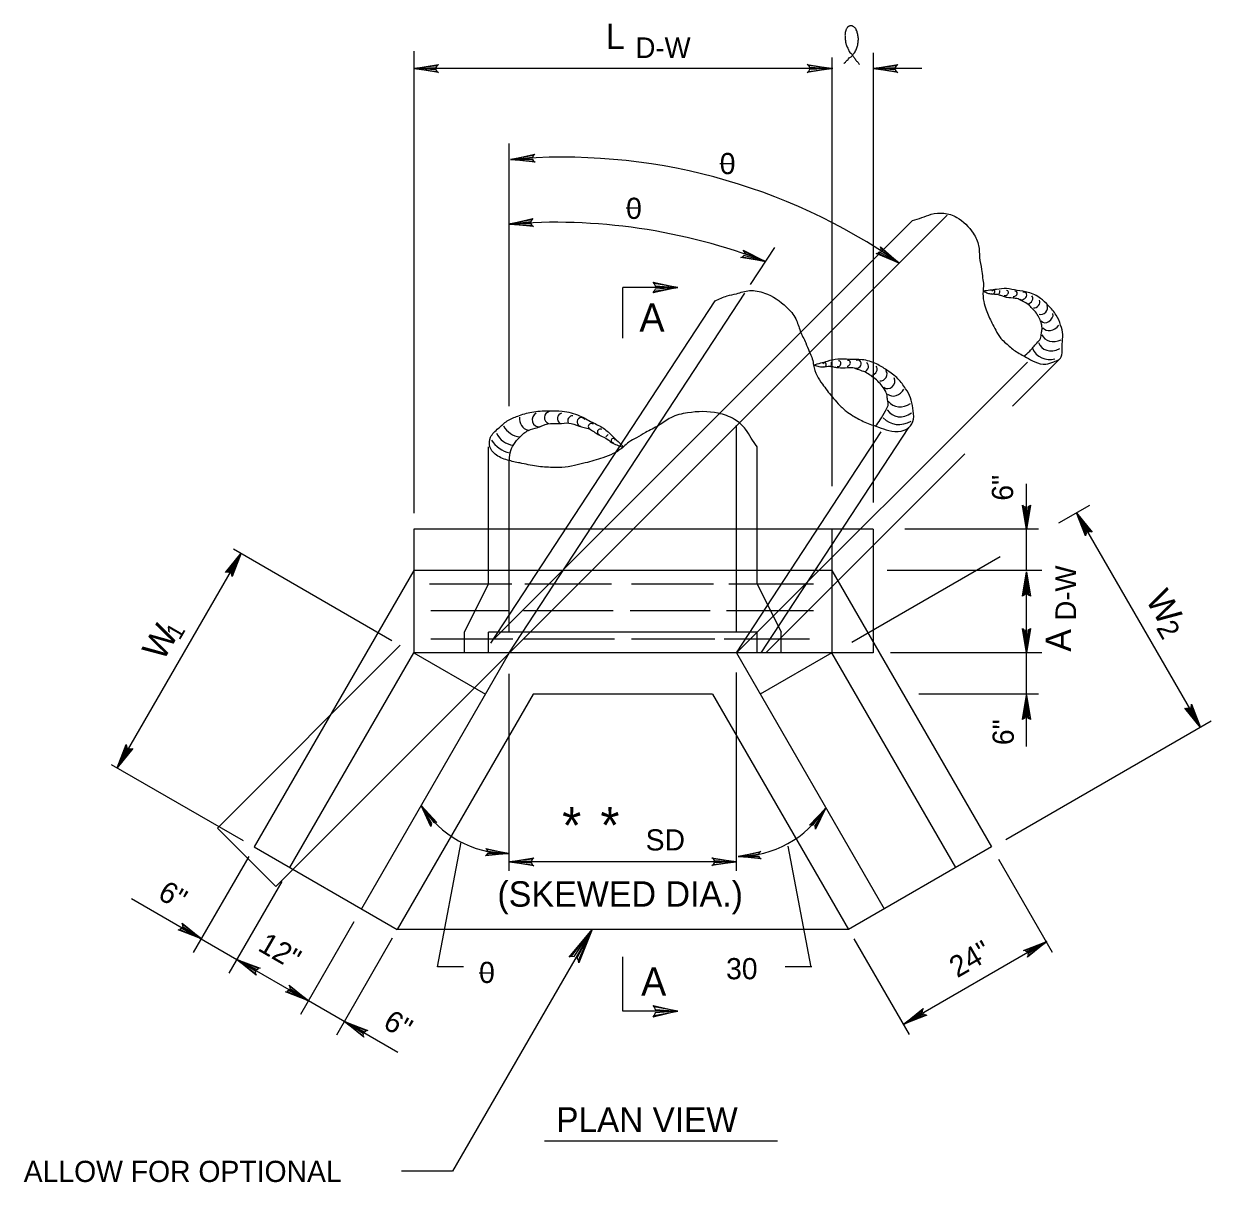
# Model space of a CAD drawing. Extents: x 638877 to 639960, y 297341 to 299123.
# Drawn here: x 639097.6 to 639265.8, y 297554.3 to 297718.4 of the extents above; entities that cross this region are included whole.
import ezdxf

# ---------------------------------------------------------------- set-up
doc = ezdxf.new("R2010")
doc.units = 0
for name, color, linetype in [('1', 7, 'Continuous'), ('2', 7, 'Continuous'), ('3', 7, 'Continuous')]:
    doc.layers.add(name, color=color, linetype=linetype)

msp = doc.modelspace()

# ---------------------------------------------------------------- linework, layer by layer
at = {"layer": '1'}
for p, q in [((639182.48, 297673.85), (639182.48, 297681.01)), ((639182.48, 297578.51), (639182.48, 297586.23))]:
    msp.add_line(p, q, dxfattribs=at)
at = {"layer": '2'}
for p, q in [((639152.88, 297714.49), (639152.88, 297649.07)), ((639212.06, 297713.59), (639212.06, 297652.88)), ((639217.91, 297714.27), (639217.91, 297650.57)), ((639212.19, 297712.03), (639152.88, 297712.03)), ((639224.79, 297712.03), (639217.91, 297712.03)), ((639166.39, 297664.23), (639166.39, 297701.43)), ((639133.32, 297596.18), (639228.39, 297691.26)), ((639164.32, 297631.32), (639223.49, 297690.49)), ((639200.55, 297681.46), (639203.98, 297686.69)), ((639190.28, 297681.01), (639182.48, 297681.01)), ((639166.39, 297629.25), (639199.75, 297680.23)), ((639163.8, 297630.64), (639195.53, 297679.13)), ((639198.56, 297629.25), (639239.75, 297670.45)), ((639237.64, 297664.2), (639244.26, 297670.81)), ((639198.56, 297632.18), (639198.56, 297661.53)), ((639202.06, 297629.25), (639222.96, 297661.19)), ((639198.56, 297629.25), (639219.04, 297660.55)), ((639163.46, 297640.95), (639163.46, 297658.46)), ((639201.49, 297640.95), (639201.49, 297658.46)), ((639166.39, 297632.18), (639166.39, 297656.31)), ((639202.7, 297629.25), (639230.89, 297657.45)), ((639220.22, 297646.77), (639227.09, 297653.64)), ((639239.63, 297640.95), (639239.63, 297653.2)), ((639248.53, 297650.15), (639244.17, 297647.63)), ((639246.73, 297649.1), (639264.28, 297618.71)), ((639211.72, 297646.8), (639152.88, 297646.8)), ((639152.88, 297646.8), (639152.88, 297629.25)), ((639217.91, 297646.8), (639211.72, 297646.8)), ((639212.06, 297646.8), (639212.06, 297629.25)), ((639217.91, 297646.8), (639217.91, 297629.25)), ((639241.35, 297646.8), (639222.38, 297646.8)), ((639127.33, 297644.01), (639149.78, 297631.04)), ((639128.41, 297643.38), (639110.86, 297612.99)), ((639235.91, 297642.86), (639214.89, 297630.72)), ((639152.88, 297640.95), (639130.26, 297601.78)), ((639212.07, 297640.95), (639152.88, 297640.95)), ((639163.46, 297639.03), (639163.46, 297640.95)), ((639201.49, 297639.04), (639201.49, 297640.95)), ((639204.76, 297633.39), (639210.08, 297641.52)), ((639212.07, 297640.95), (639234.69, 297601.78)), ((639241.79, 297640.95), (639219.91, 297640.95)), ((639239.63, 297629.26), (639239.63, 297640.75)), ((639166.74, 297639), (639155.08, 297639)), ((639160.03, 297632.18), (639163.46, 297639.03)), ((639180.88, 297639), (639168.58, 297639)), ((639195.33, 297639), (639183.68, 297639)), ((639209.47, 297639), (639197.49, 297639)), ((639201.49, 297639.04), (639204.91, 297632.18)), ((639166.42, 297635.22), (639155.29, 297635.22)), ((639181.09, 297635.22), (639168.39, 297635.22)), ((639194.82, 297635.22), (639183.49, 297635.22)), ((639209.47, 297635.22), (639197.17, 297635.22)), ((639166.9, 297631.2), (639155.29, 297631.2)), ((639160.03, 297629.25), (639160.03, 297632.18)), ((639201.49, 297632.18), (639163.46, 297632.18)), ((639163.46, 297629.25), (639163.46, 297632.18)), ((639166.39, 297632.18), (639166.39, 297632.18)), ((639181.28, 297631.2), (639168.39, 297631.2)), ((639195.49, 297631.2), (639183.68, 297631.2)), ((639208.88, 297631.2), (639196.82, 297631.2)), ((639198.56, 297632.18), (639198.56, 297632.18)), ((639201.49, 297629.25), (639201.49, 297632.18)), ((639204.91, 297629.25), (639204.91, 297632.18)), ((639125.05, 297604.46), (639150.96, 297630.37)), ((639135.33, 297598.86), (639152.88, 297629.25)), ((639166.39, 297629.25), (639145.46, 297593)), ((639212.07, 297629.25), (639152.88, 297629.25)), ((639152.88, 297629.25), (639163.01, 297623.4)), ((639166.39, 297629.25), (639166.39, 297629.25)), ((639198.56, 297629.25), (639219.49, 297593.01)), ((639198.56, 297629.25), (639198.56, 297629.25)), ((639212.07, 297629.25), (639201.94, 297623.4)), ((639217.91, 297629.25), (639212.07, 297629.25)), ((639229.62, 297598.86), (639212.07, 297629.25)), ((639241.79, 297629.25), (639220.35, 297629.25)), ((639239.63, 297616), (639239.63, 297629.25)), ((639166.39, 297598.41), (639166.39, 297626.28)), ((639198.56, 297598.41), (639198.56, 297626.47)), ((639169.77, 297623.4), (639150.53, 297590.08)), ((639195.19, 297623.4), (639169.77, 297623.4)), ((639195.19, 297623.4), (639214.43, 297590.08)), ((639241.35, 297623.4), (639224.38, 297623.4)), ((639265.79, 297619.58), (639236.69, 297602.78)), ((639110, 297613.48), (639128.72, 297602.67)), ((639133.32, 297596.18), (639125.05, 297604.46)), ((639156.23, 297584.78), (639159.59, 297602.44)), ((639129.49, 297600.44), (639121.63, 297586.83)), ((639130.26, 297601.78), (639150.53, 297590.08)), ((639209.14, 297584.76), (639205.89, 297601.88)), ((639234.69, 297601.78), (639214.43, 297590.08)), ((639234.69, 297601.78), (639214.43, 297590.08)), ((639198.56, 297599.68), (639166.39, 297599.68)), ((639235.69, 297600.06), (639243.29, 297586.9)), ((639134.18, 297596.87), (639126.7, 297583.91)), ((639112.91, 297594.47), (639127.82, 297585.86)), ((639144.4, 297591.16), (639136.83, 297578.06)), ((639149.81, 297588.84), (639141.9, 297575.13)), ((639214.43, 297590.08), (639150.53, 297590.08)), ((639178.12, 297590.08), (639158.37, 297555.86)), ((639215.19, 297588.76), (639223.02, 297575.2)), ((639242.51, 297588.39), (639222.25, 297576.68)), ((639127.81, 297585.86), (639137.97, 297580)), ((639159.91, 297584.78), (639156.23, 297584.78)), ((639209.25, 297584.78), (639205.44, 297584.78)), ((639137.96, 297580.01), (639150.59, 297572.71)), ((639190.28, 297578.51), (639182.48, 297578.51)), ((639158.37, 297555.86), (639151.13, 297555.86))]:
    msp.add_line(p, q, dxfattribs=at)
for points in [[(639156.18, 297711.61), (639156.06, 297711.85), (639152.88, 297712.03), (639156.18, 297711.61), (639156.35, 297711.47), (639152.88, 297712.03), (639156.06, 297712.18), (639156.18, 297712.42), (639152.88, 297712.03), (639156.35, 297712.58), (639156.18, 297712.42)], [(639208.76, 297712.44), (639208.88, 297712.2), (639212.06, 297712.03), (639208.76, 297712.44), (639208.59, 297712.59), (639212.06, 297712.03), (639208.88, 297711.87), (639208.77, 297711.63), (639212.06, 297712.03), (639208.59, 297711.48), (639208.77, 297711.63)], [(639221.22, 297711.61), (639221.09, 297711.85), (639217.91, 297712.03), (639221.22, 297711.61), (639221.39, 297711.47), (639217.91, 297712.03), (639221.09, 297712.18), (639221.21, 297712.42), (639217.91, 297712.03), (639221.39, 297712.58), (639221.21, 297712.42)], [(639169.87, 297698.92), (639169.74, 297699.15), (639166.55, 297699.15), (639169.87, 297698.92), (639170.05, 297698.78), (639166.55, 297699.15), (639169.72, 297699.48), (639169.82, 297699.72), (639166.55, 297699.15), (639169.99, 297699.89), (639169.82, 297699.72)], [(639169.63, 297689.8), (639169.49, 297690.03), (639166.3, 297690), (639169.63, 297689.8), (639169.81, 297689.66), (639166.3, 297690), (639169.47, 297690.36), (639169.57, 297690.61), (639166.3, 297690), (639169.73, 297690.77), (639169.57, 297690.61)], [(639199.65, 297686.12), (639199.69, 297685.86), (639202.66, 297684.71), (639199.65, 297686.12), (639199.53, 297686.31), (639202.66, 297684.71), (639199.59, 297685.54), (639199.41, 297685.35), (639202.66, 297684.71), (639199.19, 297685.25), (639199.41, 297685.35)], [(639219.02, 297686.57), (639219, 297686.3), (639221.6, 297684.47), (639219.02, 297686.57), (639218.95, 297686.78), (639221.6, 297684.47), (639218.82, 297686.02), (639218.6, 297685.88), (639221.6, 297684.47), (639218.36, 297685.84), (639218.6, 297685.88)], [(639186.92, 297681.57), (639187.05, 297681.25), (639190.28, 297681.01), (639186.92, 297681.57), (639186.75, 297681.76), (639190.28, 297681.01), (639187.05, 297680.79), (639186.93, 297680.48), (639190.28, 297681.01), (639186.75, 297680.26), (639186.93, 297680.48)], [(639240.04, 297650.03), (639239.8, 297649.91), (639239.63, 297646.73), (639240.04, 297650.03), (639240.19, 297650.2), (639239.63, 297646.73), (639239.47, 297649.91), (639239.23, 297650.02), (639239.63, 297646.73), (639239.08, 297650.2), (639239.23, 297650.02)], [(639248.02, 297646.03), (639248.17, 297646.26), (639246.73, 297649.1), (639248.02, 297646.03), (639247.98, 297645.82), (639246.73, 297649.1), (639248.45, 297646.43), (639248.71, 297646.45), (639246.73, 297649.1), (639248.94, 297646.37), (639248.71, 297646.45)], [(639126.4, 297640.73), (639126.67, 297640.72), (639128.41, 297643.38), (639126.4, 297640.73), (639126.19, 297640.65), (639128.41, 297643.38), (639126.96, 297640.55), (639127.1, 297640.33), (639128.41, 297643.38), (639127.15, 297640.1), (639127.1, 297640.33)], [(639239.21, 297637.45), (639239.45, 297637.57), (639239.63, 297640.75), (639239.21, 297637.45), (639239.07, 297637.28), (639239.63, 297640.75), (639239.78, 297637.57), (639240.02, 297637.46), (639239.63, 297640.75), (639240.18, 297637.28), (639240.02, 297637.46)], [(639240.04, 297632.56), (639239.8, 297632.44), (639239.63, 297629.26), (639240.04, 297632.56), (639240.19, 297632.73), (639239.63, 297629.26), (639239.47, 297632.44), (639239.23, 297632.55), (639239.63, 297629.26), (639239.08, 297632.73), (639239.23, 297632.55)], [(639239.21, 297619.98), (639239.45, 297620.1), (639239.63, 297623.28), (639239.21, 297619.98), (639239.07, 297619.81), (639239.63, 297623.28), (639239.78, 297620.1), (639240.02, 297619.98), (639239.63, 297623.28), (639240.18, 297619.81), (639240.02, 297619.98)], [(639262.98, 297621.78), (639262.84, 297621.55), (639264.28, 297618.71), (639262.98, 297621.78), (639263.02, 297622), (639264.28, 297618.71), (639262.55, 297621.38), (639262.29, 297621.37), (639264.28, 297618.71), (639262.06, 297621.44), (639262.29, 297621.37)], [(639112.87, 297615.64), (639112.6, 297615.65), (639110.86, 297612.99), (639112.87, 297615.64), (639113.09, 297615.72), (639110.86, 297612.99), (639112.32, 297615.82), (639112.17, 297616.04), (639110.86, 297612.99), (639112.12, 297616.27), (639112.17, 297616.04)], [(639169.69, 297599.26), (639169.57, 297599.5), (639166.39, 297599.68), (639169.69, 297599.26), (639169.86, 297599.12), (639166.39, 297599.68), (639169.57, 297599.83), (639169.68, 297600.07), (639166.39, 297599.68), (639169.86, 297600.23), (639169.68, 297600.07)], [(639195.26, 297600.09), (639195.38, 297599.85), (639198.56, 297599.68), (639195.26, 297600.09), (639195.08, 297600.24), (639198.56, 297599.68), (639195.38, 297599.52), (639195.26, 297599.28), (639198.56, 297599.68), (639195.08, 297599.13), (639195.26, 297599.28)], [(639120.13, 297590.78), (639120.12, 297590.51), (639122.79, 297588.77), (639120.13, 297590.78), (639120.06, 297590.99), (639122.79, 297588.77), (639119.96, 297590.22), (639119.74, 297590.07), (639122.79, 297588.77), (639119.5, 297590.02), (639119.74, 297590.07)], [(639175.17, 297586.3), (639175.56, 297586.27), (639178.12, 297590.08), (639175.17, 297586.3), (639174.87, 297586.19), (639178.12, 297590.08), (639175.97, 297586.03), (639176.18, 297585.71), (639178.12, 297590.08), (639176.24, 297585.37), (639176.18, 297585.71)], [(639239.44, 297587.09), (639239.67, 297586.95), (639242.51, 297588.39), (639239.44, 297587.09), (639239.22, 297587.13), (639242.51, 297588.39), (639239.84, 297586.66), (639239.85, 297586.4), (639242.51, 297588.39), (639239.78, 297586.17), (639239.85, 297586.4)], [(639130.47, 297583.85), (639130.48, 297584.12), (639127.81, 297585.86), (639130.47, 297583.85), (639130.54, 297583.64), (639127.81, 297585.86), (639130.65, 297584.41), (639130.87, 297584.56), (639127.81, 297585.86), (639131.1, 297584.6), (639130.87, 297584.56)], [(639135.32, 297582.01), (639135.3, 297581.74), (639137.97, 297580), (639135.32, 297582.01), (639135.24, 297582.22), (639137.97, 297580), (639135.14, 297581.45), (639134.92, 297581.31), (639137.97, 297580), (639134.68, 297581.26), (639134.92, 297581.31)], [(639186.92, 297579.13), (639187.05, 297578.78), (639190.28, 297578.51), (639186.92, 297579.13), (639186.75, 297579.34), (639190.28, 297578.51), (639187.05, 297578.28), (639186.93, 297577.93), (639190.28, 297578.51), (639186.75, 297577.69), (639186.93, 297577.93)], [(639225.32, 297577.98), (639225.09, 297578.12), (639222.25, 297576.68), (639225.32, 297577.98), (639225.54, 297577.94), (639222.25, 297576.68), (639224.92, 297578.41), (639224.9, 297578.67), (639222.25, 297576.68), (639224.98, 297578.9), (639224.9, 297578.67)], [(639145.72, 297575.05), (639145.73, 297575.32), (639143.06, 297577.06), (639145.72, 297575.05), (639145.79, 297574.84), (639143.06, 297577.06), (639145.89, 297575.61), (639146.11, 297575.75), (639143.06, 297577.06), (639146.35, 297575.8), (639146.11, 297575.75)]]:
    msp.add_lwpolyline(points, dxfattribs=at)
for centre, radius, start, end in [((639173.91, 297616.19), 83.29, 55.0628, 95.0689), ((639172.79, 297606.96), 83.29, 68.9781, 94.4657), ((639242.89, 297673.45), 2.64, 203.6502, 287.1187), ((639169.44, 297662.39), 1.62, 171.4216, 257.1702), ((639170.63, 297662.29), 1.01, 114.5127, 278.9205), ((639172.23, 297662.58), 0.87, 101.4984, 250.2996), ((639173.97, 297662.46), 0.763, 103.3175, 237.589), ((639175.38, 297662.15), 0.707, 87.6701, 208.6596), ((639176.59, 297661.97), 0.614, 37.1633, 261.4544), ((639168.13, 297662.74), 2.87, 207.4769, 265.7651), ((639178, 297661.34), 0.423, 46.1947, 246.6659), ((639179.28, 297660.55), 0.419, 56.1449, 254.2438), ((639167.26, 297661.57), 4.04, 212.4871, 258.5153), ((639167.21, 297661.54), 2.86, 204.0664, 264.9023), ((639180.78, 297659.6), 0.723, 124.194, 164.3926), ((639181.11, 297659.35), 0.307, 356.947, 273.053)]:
    msp.add_arc(centre, radius, start, end, dxfattribs=at)
for centre, major_axis, ratio, start_param, end_param in [((639234.89, 297680.36), (-0.217, -0.217), 0.747225, 6.2299, 11.048859), ((639235.24, 297680.36), (0.511, 0.511), 0.747225, 4.984789, 5.686388), ((639236.7, 297680.23), (0.296, 0.296), 0.747225, 3.416591, 6.874068), ((639237.94, 297680.12), (0.299, 0.299), 0.747225, 3.548849, 7.047733), ((639239.12, 297679.82), (0.434, 0.434), 0.747225, 3.290742, 7.20536), ((639239.9, 297679.31), (0.5, 0.5), 0.747225, 3.90445, 6.32385), ((639240.86, 297678.79), (0.54, 0.54), 0.747225, 3.707271, 6.050752), ((639241.86, 297677.95), (0.615, 0.615), 0.747225, 3.485429, 6.082501), ((639242.51, 297676.9), (-0.712, -0.712), 0.747225, 6.127494, 8.996951), ((639244.14, 297675.89), (-2.03, -2.03), 0.747225, 6.018782, 7.374419), ((639243.2, 297676.34), (-1.14, -1.14), 0.747225, 6.164658, 8.003702), ((639243.78, 297674.56), (-2.02, -2.02), 0.747225, 5.914861, 7.433944), ((639211.01, 297670.07), (-0.168, -0.257), 0.851006, 6.2299, 11.048859), ((639211.38, 297670.13), (0.396, 0.605), 0.851006, 4.984789, 5.686388), ((639212.97, 297670.22), (0.229, 0.35), 0.851006, 3.416591, 6.874068), ((639214.31, 297670.29), (0.232, 0.354), 0.851006, 3.548849, 7.047733), ((639215.66, 297670.16), (0.336, 0.513), 0.851006, 3.290742, 7.20536), ((639216.63, 297669.75), (0.387, 0.591), 0.851006, 3.90445, 6.32385), ((639217.8, 297669.35), (0.418, 0.639), 0.851006, 3.707271, 6.050752), ((639219.1, 297668.64), (0.476, 0.728), 0.851006, 3.485429, 6.082501), ((639220.09, 297667.65), (-0.551, -0.843), 0.851007, 6.127494, 8.996951), ((639220.99, 297667.18), (-0.89, -1.35), 0.851006, 6.164658, 8.003702), ((639222.11, 297666.86), (-1.57, -2.4), 0.851006, 6.018782, 7.374419), ((639222.08, 297665.48), (-2.21, -3.38), 0.851007, 6.082315, 7.286974), ((639222.11, 297665.43), (-1.56, -2.39), 0.851006, 5.914861, 7.433944)]:
    msp.add_ellipse(centre, major_axis=major_axis, ratio=ratio, start_param=start_param, end_param=end_param, dxfattribs=at)
for points in [[(639223.49, 297690.49), (639224.8, 297690.91), (639226.12, 297691.38), (639227.92, 297691.54), (639229.77, 297690.94), (639232.09, 297688.69), (639232.85, 297686.94), (639232.99, 297685.25), (639233.27, 297683.58), (639233.42, 297682.38), (639233.54, 297681.35), (639233.48, 297680.5), (639233.57, 297679.05), (639233.94, 297677.84), (639234.73, 297676), (639235.28, 297674.96), (639236.02, 297673.81), (639236.72, 297673.11), (639238.03, 297672.04), (639239.61, 297671.12), (639240.81, 297670.48), (639242.37, 297670.15), (639243.48, 297670.5), (639244.26, 297670.81), (639244.7, 297672.98), (639244.77, 297674.38), (639244.47, 297675.67), (639243.83, 297677.11), (639242.71, 297678.48), (639241.62, 297679.48), (639239.89, 297680.32), (639238.29, 297680.61), (639236.82, 297680.85), (639235.38, 297680.74), (639233.48, 297680.5)], [(639195.53, 297679.13), (639197.25, 297679.83), (639198.55, 297680.14), (639200.42, 297680.57), (639202.54, 297680.23), (639205.66, 297678.25), (639206.96, 297676.57), (639207.6, 297674.85), (639208.37, 297673.16), (639208.87, 297671.94), (639209.3, 297670.9), (639209.48, 297670.01), (639209.98, 297668.52), (639210.73, 297667.34), (639212.09, 297665.55), (639212.97, 297664.56), (639214.09, 297663.48), (639215.03, 297662.86), (639216.73, 297661.96), (639218.67, 297661.24), (639220.13, 297660.77), (639221.88, 297660.67), (639222.96, 297661.19), (639223.62, 297662.35), (639223.54, 297663.93), (639223.21, 297665.39), (639222.52, 297666.67), (639221.43, 297668.07), (639219.84, 297669.32), (639218.41, 297670.18), (639216.34, 297670.79), (639214.55, 297670.84), (639212.93, 297670.87), (639211.42, 297670.55), (639209.48, 297670.01)], [(639239.24, 297671.25), (639240.09, 297672.02), (639241.09, 297673.15), (639241.6, 297673.78), (639241.74, 297674.54), (639241.83, 297675.11), (639241.76, 297675.84), (639241.46, 297676.63), (639241.04, 297677.37), (639240.44, 297678.05), (639239.89, 297678.6), (639239.15, 297679.02), (639238.43, 297679.4), (639237.75, 297679.51), (639236.52, 297679.69), (639236.02, 297679.86), (639235.56, 297680), (639234.59, 297680.07), (639234.01, 297680.23), (639233.48, 297680.5)], [(639218.24, 297661.33), (639218.92, 297662.25), (639219.66, 297663.57), (639220.02, 297664.3), (639219.96, 297665.1), (639219.88, 297665.7), (639219.6, 297666.44), (639219.05, 297667.21), (639218.4, 297667.92), (639217.57, 297668.53), (639216.83, 297669.01), (639215.92, 297669.34), (639215.05, 297669.62), (639214.29, 297669.63), (639212.94, 297669.63), (639212.35, 297669.73), (639211.82, 297669.81), (639210.78, 297669.73), (639210.12, 297669.81), (639209.48, 297670.01)], [(639201.49, 297658.46), (639200.65, 297659.68), (639199.84, 297660.95), (639198.28, 297662.34), (639195.97, 297663.21), (639191.64, 297663.26), (639189.27, 297662.57), (639187.54, 297661.47), (639185.69, 297660.49), (639184.41, 297659.74), (639183.32, 297659.1), (639182.57, 297658.46), (639181.12, 297657.49), (639179.62, 297656.91), (639177.14, 297656.16), (639175.64, 297655.81), (639173.84, 297655.52), (639172.52, 297655.52), (639170.26, 297655.7), (639167.89, 297656.16), (639166.16, 297656.56), (639164.37, 297657.43), (639163.65, 297658.46), (639163.74, 297659.8), (639164.84, 297661.07), (639166.1, 297662.11), (639167.6, 297662.81), (639169.57, 297663.38), (639171.94, 297663.56), (639173.9, 297663.49), (639176.33, 297662.86), (639178.12, 297661.94), (639179.74, 297661.07), (639181.01, 297659.97), (639182.57, 297658.46)], [(639166.39, 297656.31), (639166.52, 297657.59), (639167.03, 297658.8), (639167.89, 297659.84), (639169.1, 297660.78), (639170.41, 297661.21), (639171.83, 297661.7), (639173.47, 297661.74), (639174.8, 297661.82), (639176.27, 297661.38), (639177.7, 297660.99), (639179, 297660.18), (639180.06, 297659.67), (639180.88, 297659.07), (639182.4, 297658.46)]]:
    msp.add_spline(points, degree=3, dxfattribs=at)
at = {"layer": '3'}
for p, q in [((639196.19, 297698.58), (639198.14, 297698.58)), ((639182.94, 297692.31), (639184.89, 297692.31)), ((639162.11, 297583.95), (639164.05, 297583.95)), ((639171.37, 297560.18), (639204.37, 297560.18))]:
    msp.add_line(p, q, dxfattribs=at)
for points in [[(639155.31, 297604.88), (639155.43, 297605.1), (639153.91, 297607.64), (639155.31, 297604.88), (639155.28, 297604.67), (639153.91, 297607.64), (639155.68, 297605.27), (639155.93, 297605.3), (639153.91, 297607.64), (639156.14, 297605.25), (639155.93, 297605.3)], [(639209.11, 297604.91), (639209.36, 297604.88), (639211.15, 297607.24), (639209.11, 297604.91), (639208.91, 297604.86), (639211.15, 297607.24), (639209.62, 297604.71), (639209.74, 297604.5), (639211.15, 297607.24), (639209.76, 297604.28), (639209.74, 297604.5)], [(639163.22, 297601.4), (639163.32, 297601.17), (639166.26, 297600.84), (639163.22, 297601.4), (639163.07, 297601.54), (639166.26, 297600.84), (639163.3, 297600.86), (639163.18, 297600.65), (639166.26, 297600.84), (639163.01, 297600.51), (639163.18, 297600.65)], [(639201.88, 297600.23), (639201.76, 297600.44), (639198.8, 297600.44), (639201.88, 297600.23), (639202.05, 297600.1), (639198.8, 297600.44), (639201.74, 297600.75), (639201.83, 297600.98), (639198.8, 297600.44), (639201.99, 297601.13), (639201.83, 297600.98)]]:
    msp.add_lwpolyline(points, dxfattribs=at)
for centre, start, end in [((639166.33, 297615.58), 212.596, 269.7176), ((639198.72, 297615.18), 270.2824, 327.404)]:
    msp.add_arc(centre, 14.75, start, end, dxfattribs=at)
msp.add_spline([(639213.75, 297712.75), (639213.98, 297712.95), (639214.12, 297713.1), (639214.36, 297713.32), (639214.54, 297713.52), (639214.86, 297713.75), (639215.09, 297714.05), (639215.29, 297714.27), (639215.43, 297714.54), (639215.56, 297714.83), (639215.64, 297715.1), (639215.74, 297715.36), (639215.77, 297715.58), (639215.81, 297715.88), (639215.82, 297716.13), (639215.81, 297716.41), (639215.75, 297716.7), (639215.7, 297716.98), (639215.63, 297717.25), (639215.53, 297717.51), (639215.45, 297717.66), (639215.34, 297717.78), (639215.23, 297717.88), (639215.11, 297717.98), (639214.99, 297718.05), (639214.89, 297718.08), (639214.69, 297718.08), (639214.58, 297718.05), (639214.41, 297717.99), (639214.3, 297717.9), (639214.23, 297717.8), (639214.16, 297717.66), (639214.08, 297717.54), (639214.04, 297717.37), (639214, 297717.25), (639213.95, 297716.97), (639213.93, 297716.77), (639213.95, 297716.55), (639213.95, 297716.32), (639214, 297716), (639214.02, 297715.74), (639214.06, 297715.54), (639214.15, 297715.29), (639214.26, 297715.03), (639214.37, 297714.8), (639214.48, 297714.58), (639214.62, 297714.31), (639214.85, 297714.11), (639214.99, 297713.87), (639215.14, 297713.69), (639215.27, 297713.48), (639215.43, 297713.28), (639215.58, 297713.08), (639215.71, 297712.96), (639215.84, 297712.8), (639215.96, 297712.61)], degree=3, dxfattribs=at)

# ---------------------------------------------------------------- texts
at = {"layer": '1'}
for s, height, p in [('D-W', 2.916, (639184.27, 297713.52)), ('*', 5.19, (639173.88, 297602.24)), ('*', 5.19, (639179.29, 297602.27)), ('ALLOW FOR OPTIONAL', 2.9999, (639097.63, 297554.33))]:
    msp.add_text(s, height=height, dxfattribs=at).set_placement(p)
msp.add_text('D-W', height=2.916, rotation=90, dxfattribs=at).set_placement((639246.65, 297633.84))
at = {"layer": '3'}
for s, height, p in [('L', 3.6, (639180.05, 297714.77)), ('0', 3, (639196.19, 297697.07)), ('0', 3, (639182.93, 297690.73)), ('A', 3.99, (639184.82, 297674.77)), ('SD', 3, (639185.7, 297601.28)), ('(SKEWED DIA.)', 3.5999, (639164.71, 297593.32)), ('0', 3, (639162.11, 297582.51)), ('30', 3, (639197.09, 297583.04)), ('A', 3.99, (639185.06, 297580.72)), ('PLAN VIEW', 3.53, (639173.04, 297561.39))]:
    msp.add_text(s, height=height, dxfattribs=at).set_placement(p)
for s, height, rotation, p in [('6"', 3, 90, (639237.73, 297650.82)), ('W', 3.6, 300.0044, (639256.4, 297636.86)), ('W', 3.6, 60.0051, (639117.35, 297627.95)), ('1', 2.43, 59.9689, (639119.7, 297630.96)), ('A', 3.6, 90, (639245.93, 297629.43)), ('2', 2.92, 300.0109, (639257.91, 297632.81)), ('6"', 3, 90, (639237.83, 297616.2)), ('6"', 3, 329.9938, (639116.44, 297594.56)), ('12"', 3, 329.9938, (639130.63, 297587.21)), ('24"', 3, 30.0062, (639229.83, 297583.17)), ('6"', 3, 329.9938, (639148.34, 297576.26))]:
    msp.add_text(s, height=height, rotation=rotation, dxfattribs=at).set_placement(p)

doc.saveas('drawing.dxf')
